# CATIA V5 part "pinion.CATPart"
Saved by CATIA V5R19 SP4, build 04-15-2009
Part number: pinion
Bounding box of the stored display mesh (mm): x 0 to 22.15, y -19 to 19, z -18.807 to 18.807
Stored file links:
  G:\EU_thinkMotion\CFAO_2010\MMS_groupe1\MMS_groupe1\A reprendre\OK\rdeneffle\pinion.CATPart
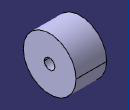
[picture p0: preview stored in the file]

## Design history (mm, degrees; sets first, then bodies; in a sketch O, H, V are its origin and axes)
Parameters
  `rayon exterieur pinion` = 19 mm
  `rayon interieur pinion` = 3.85 mm
Body1 (main body)
  Sketch1 on yz-plane, origin (0, 0, 0), H (0, 1, 0), V (0, 0, 1)
    circle A1 centre (0, 0) radius 3.85
    circle A2 centre (0, 0) radius 19
    radius A2 = 19 {= `rayon exterieur pinion`}
    radius A1 = 3.85 {= `rayon interieur pinion`}
  Pad1: profile Sketch1, direction (1, 0, 0), length 22.15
